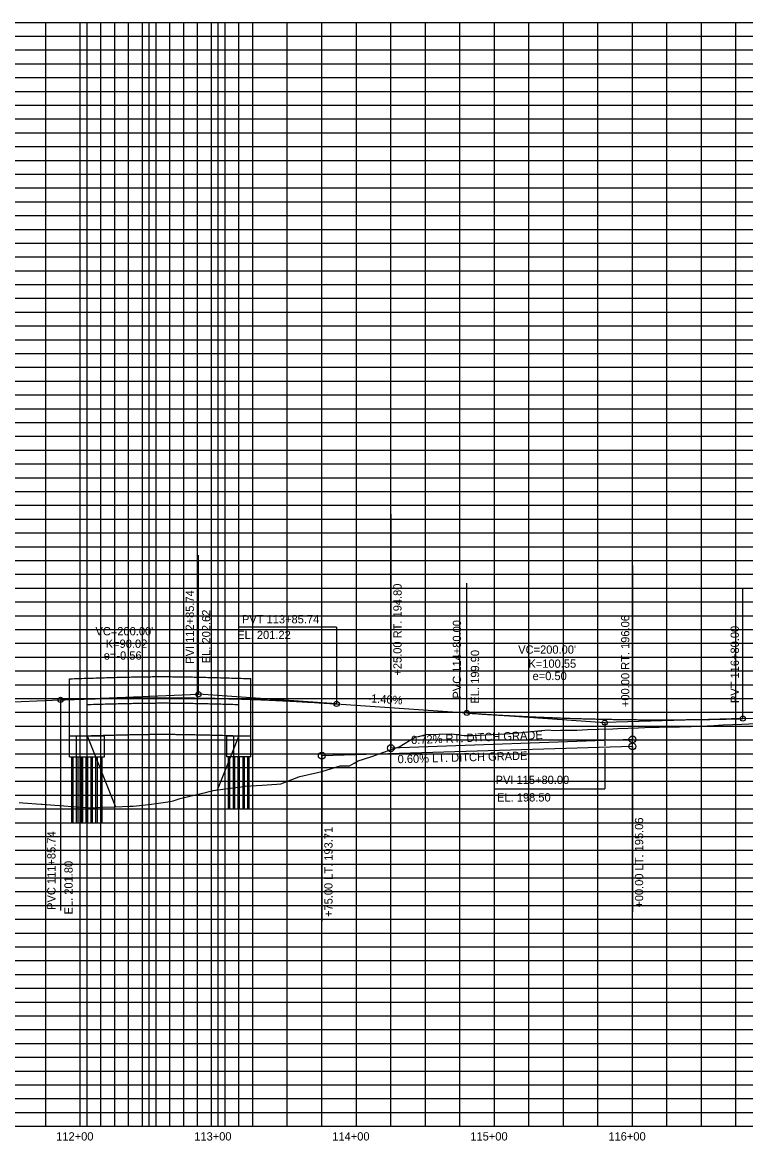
# Model space of a CAD drawing. Extents: x 1384498 to 1391279, y 1965973 to 1976560.
# Drawn here: x 1389607 to 1390131, y 1975299 to 1976110 of the extents above; entities that cross this region are included whole.
import ezdxf

# ---------------------------------------------------------------- set-up
doc = ezdxf.new("R2010")
doc.units = 0
for name, color, linetype in [('Default', 7, 'Continuous'), ('R_Axis_Annotation', 7, 'Continuous'), ('R_Driveway', 7, 'Continuous'), ('R_Exist Surface', 7, 'Continuous'), ('R_Grid', 7, 'Continuous'), ('R_Grid_Minor', 7, 'Continuous'), ('R_Vert Alg', 7, 'Continuous'), ('R_Vert Alg Annot', 7, 'Continuous')]:
    doc.layers.add(name, color=color, linetype=linetype)

msp = doc.modelspace()

# ---------------------------------------------------------------- linework, layer by layer
at = {"layer": 'Default'}
for p, q in [((1389653.79, 1975309.84), (1389653.79, 1976109.84)), ((1389663.79, 1975309.84), (1389663.79, 1976109.84)), ((1389673.79, 1975309.84), (1389673.79, 1976109.84)), ((1389683.79, 1975309.84), (1389683.79, 1976109.84)), ((1389693.79, 1975309.84), (1389693.79, 1976109.84)), ((1389703.79, 1975309.84), (1389703.79, 1976109.84)), ((1389713.79, 1975309.84), (1389713.79, 1976109.84)), ((1389723.79, 1975309.84), (1389723.79, 1976109.84)), ((1389733.79, 1975309.84), (1389733.79, 1976109.84)), ((1389743.79, 1975309.84), (1389743.79, 1976109.84)), ((1389753.79, 1975309.84), (1389753.79, 1976109.84)), ((1389763.79, 1975309.84), (1389763.79, 1976109.84)), ((1388248.79, 1975309.84), (1390648.79, 1975309.84))]:
    msp.add_line(p, q, dxfattribs=at)
at = {"layer": 'R_Driveway'}
for p, q in [((1389641.1, 1975577.58), (1389641.1, 1975634.09)), ((1389653.79, 1975592.82), (1389653.79, 1975634.51)), ((1389763.79, 1975592.8), (1389763.79, 1975634.49)), ((1389772.42, 1975577.54), (1389772.42, 1975634.21)), ((1389666.28, 1975592.59), (1389641.1, 1975592.59)), ((1389646.1, 1975577.58), (1389646.1, 1975592.59)), ((1389653.79, 1975592.82), (1389674.37, 1975541.36)), ((1389666.28, 1975577.58), (1389666.28, 1975592.59)), ((1389763.79, 1975592.8), (1389748.05, 1975553.46)), ((1389755.09, 1975577.54), (1389755.09, 1975592.54)), ((1389772.42, 1975592.54), (1389755.09, 1975592.54)), ((1389760.09, 1975577.54), (1389760.09, 1975592.54)), ((1389641.1, 1975577.58), (1389666.28, 1975577.58)), ((1389642.69, 1975529.84), (1389642.69, 1975577.58)), ((1389643.69, 1975529.84), (1389643.69, 1975577.58)), ((1389646.19, 1975529.84), (1389646.19, 1975577.58)), ((1389647.19, 1975529.84), (1389647.19, 1975577.58)), ((1389649.69, 1975529.84), (1389649.69, 1975577.58)), ((1389650.69, 1975529.84), (1389650.69, 1975577.58)), ((1389653.19, 1975529.84), (1389653.19, 1975577.58)), ((1389654.19, 1975529.84), (1389654.19, 1975577.58)), ((1389656.69, 1975529.84), (1389656.69, 1975577.58)), ((1389657.69, 1975529.84), (1389657.69, 1975577.58)), ((1389660.19, 1975529.84), (1389660.19, 1975577.58)), ((1389661.19, 1975529.84), (1389661.19, 1975577.58)), ((1389663.69, 1975529.84), (1389663.69, 1975577.58)), ((1389664.69, 1975529.84), (1389664.69, 1975577.58)), ((1389772.42, 1975577.54), (1389755.09, 1975577.54)), ((1389756.26, 1975539.84), (1389756.26, 1975577.54)), ((1389757.26, 1975539.84), (1389757.26, 1975577.54)), ((1389759.76, 1975539.84), (1389759.76, 1975577.54)), ((1389760.76, 1975539.84), (1389760.76, 1975577.54)), ((1389763.26, 1975539.84), (1389763.26, 1975577.54)), ((1389764.26, 1975539.84), (1389764.26, 1975577.54)), ((1389766.76, 1975539.84), (1389766.76, 1975577.54)), ((1389767.76, 1975539.84), (1389767.76, 1975577.54)), ((1389770.26, 1975539.84), (1389770.26, 1975577.54)), ((1389771.26, 1975539.84), (1389771.26, 1975577.54))]:
    msp.add_line(p, q, dxfattribs=at)
for points in [[(1389641.1, 1975634.09), (1389684.85, 1975635.67), (1389728.66, 1975635.71), (1389772.42, 1975634.21)], [(1389653.79, 1975615.5), (1389690.44, 1975616.58), (1389727.13, 1975616.58), (1389763.79, 1975615.48)], [(1389653.79, 1975592.82), (1389690.44, 1975593.92), (1389727.13, 1975593.91), (1389763.79, 1975592.8)]]:
    msp.add_open_spline(points, degree=2, dxfattribs=at)
at = {"layer": 'R_Exist Surface'}
for points in [[(1389604.55, 1975544.36), (1389607.11, 1975544.19), (1389620.46, 1975543.28), (1389621.27, 1975543.22), (1389630.42, 1975542.53), (1389633.8, 1975542.27), (1389646.19, 1975541.31), (1389647.14, 1975541.24), (1389649.33, 1975541.07), (1389650.5, 1975540.99), (1389654.54, 1975540.65), (1389660.49, 1975540.85), (1389664.17, 1975540.97), (1389673.58, 1975541.33), (1389673.83, 1975541.34), (1389684.72, 1975541.74), (1389687.17, 1975541.84), (1389689.66, 1975541.93), (1389700.52, 1975543.29), (1389703.65, 1975543.68), (1389703.72, 1975543.69), (1389703.83, 1975543.7), (1389713.86, 1975545.27), (1389716.07, 1975545.61), (1389721.23, 1975547.36), (1389727.2, 1975548.78), (1389740.55, 1975551.96), (1389742.24, 1975552.37), (1389743.84, 1975552.74), (1389744.34, 1975552.85), (1389745.07, 1975553.05), (1389753.89, 1975554.27), (1389767.23, 1975556.12), (1389768.28, 1975556.26), (1389780.58, 1975557.06), (1389791.32, 1975557.77), (1389793.92, 1975558.06), (1389794.14, 1975558.09), (1389807.26, 1975563.08), (1389807.98, 1975563.35), (1389820.61, 1975566.15), (1389823.8, 1975566.84), (1389833.95, 1975570.11), (1389837.03, 1975571.11), (1389843.79, 1975571.13), (1389847.29, 1975573.04), (1389850.22, 1975574.59), (1389853.92, 1975575.98), (1389860.64, 1975578.15), (1389864.54, 1975579.38), (1389872.73, 1975582.48), (1389879.84, 1975584.82), (1389891.75, 1975591.94), (1389893.9, 1975592.21), (1389899.41, 1975593.85), (1389917.54, 1975594.13), (1389917.62, 1975594.13), (1389917.62, 1975594.13), (1389917.65, 1975594.11), (1389917.71, 1975594.11), (1389926.8, 1975593.11), (1389932.54, 1975592.96), (1389938.09, 1975593.21), (1389960.46, 1975594.49), (1389962.65, 1975594.59), (1389966.32, 1975594.88), (1389975.1, 1975596), (1389985.37, 1975596.96), (1389987.73, 1975597.1), (1389991.74, 1975596.6), (1389996.76, 1975596.89), (1390008.49, 1975596.99), (1390016.3, 1975597.39), (1390024.26, 1975597.51), (1390034.55, 1975597.91), (1390038.23, 1975598.07), (1390053.02, 1975598.67), (1390053.11, 1975598.68), (1390057.73, 1975598.79), (1390067.77, 1975599.04), (1390068.15, 1975599.06), (1390082.82, 1975599.24)], [(1390082.82, 1975599.24), (1390091.38, 1975599.54), (1390098.09, 1975599.78), (1390107.69, 1975600.34), (1390110.87, 1975600.5), (1390113.11, 1975600.58), (1390114.47, 1975600.68), (1390128.08, 1975601.16), (1390138.24, 1975601.8)]]:
    msp.add_lwpolyline(points, dxfattribs=at)
at = {"layer": 'R_Grid'}
for p, q in [((1388248.79, 1976109.84), (1391048.79, 1976109.84)), ((1388248.79, 1976109.84), (1391048.79, 1976109.84)), ((1389648.79, 1975309.84), (1389648.79, 1976109.84)), ((1389748.79, 1975309.84), (1389748.79, 1976109.84)), ((1389848.79, 1975309.84), (1389848.79, 1976109.84)), ((1389948.79, 1975309.84), (1389948.79, 1976109.84)), ((1390048.79, 1975309.84), (1390048.79, 1976109.84)), ((1388248.79, 1976059.84), (1391048.79, 1976059.84)), ((1388248.79, 1976009.84), (1391048.79, 1976009.84)), ((1388248.79, 1975959.84), (1391048.79, 1975959.84)), ((1388248.79, 1975909.84), (1391048.79, 1975909.84)), ((1388248.79, 1975859.84), (1391048.79, 1975859.84)), ((1388248.79, 1975809.84), (1391048.79, 1975809.84)), ((1388248.79, 1975759.84), (1391048.79, 1975759.84)), ((1388248.79, 1975709.84), (1391048.79, 1975709.84)), ((1388248.79, 1975659.84), (1391048.79, 1975659.84)), ((1388248.79, 1975609.84), (1391048.79, 1975609.84)), ((1388248.79, 1975559.84), (1391048.79, 1975559.84)), ((1388248.79, 1975509.84), (1391048.79, 1975509.84)), ((1388248.79, 1975459.84), (1391048.79, 1975459.84)), ((1388248.79, 1975409.84), (1391048.79, 1975409.84)), ((1388248.79, 1975359.84), (1391048.79, 1975359.84)), ((1388248.79, 1975309.84), (1391048.79, 1975309.84))]:
    msp.add_line(p, q, dxfattribs=at)
at = {"layer": 'R_Grid_Minor'}
for p, q in [((1389623.79, 1975309.84), (1389623.79, 1976109.84)), ((1389673.79, 1975309.84), (1389673.79, 1976109.84)), ((1389698.79, 1975309.84), (1389698.79, 1976109.84)), ((1389723.79, 1975309.84), (1389723.79, 1976109.84)), ((1389773.79, 1975309.84), (1389773.79, 1976109.84)), ((1389798.79, 1975309.84), (1389798.79, 1976109.84)), ((1389823.79, 1975309.84), (1389823.79, 1976109.84)), ((1389873.79, 1975309.84), (1389873.79, 1976109.84)), ((1389898.79, 1975309.84), (1389898.79, 1976109.84)), ((1389923.79, 1975309.84), (1389923.79, 1976109.84)), ((1389973.79, 1975309.84), (1389973.79, 1976109.84)), ((1389998.79, 1975309.84), (1389998.79, 1976109.84)), ((1390023.79, 1975309.84), (1390023.79, 1976109.84)), ((1390073.79, 1975309.84), (1390073.79, 1976109.84)), ((1390098.79, 1975309.84), (1390098.79, 1976109.84)), ((1390123.79, 1975309.84), (1390123.79, 1976109.84)), ((1388248.79, 1976099.84), (1391048.79, 1976099.84)), ((1388248.79, 1976089.84), (1391048.79, 1976089.84)), ((1388248.79, 1976079.84), (1391048.79, 1976079.84)), ((1388248.79, 1976069.84), (1391048.79, 1976069.84)), ((1388248.79, 1976049.84), (1391048.79, 1976049.84)), ((1388248.79, 1976039.84), (1391048.79, 1976039.84)), ((1388248.79, 1976029.84), (1391048.79, 1976029.84)), ((1388248.79, 1976019.84), (1391048.79, 1976019.84)), ((1388248.79, 1975999.84), (1391048.79, 1975999.84)), ((1388248.79, 1975989.84), (1391048.79, 1975989.84)), ((1388248.79, 1975979.84), (1391048.79, 1975979.84)), ((1388248.79, 1975969.84), (1391048.79, 1975969.84)), ((1388248.79, 1975949.84), (1391048.79, 1975949.84)), ((1388248.79, 1975939.84), (1391048.79, 1975939.84)), ((1388248.79, 1975929.84), (1391048.79, 1975929.84)), ((1388248.79, 1975919.84), (1391048.79, 1975919.84)), ((1388248.79, 1975899.84), (1391048.79, 1975899.84)), ((1388248.79, 1975889.84), (1391048.79, 1975889.84)), ((1388248.79, 1975879.84), (1391048.79, 1975879.84)), ((1388248.79, 1975869.84), (1391048.79, 1975869.84)), ((1388248.79, 1975849.84), (1391048.79, 1975849.84)), ((1388248.79, 1975839.84), (1391048.79, 1975839.84)), ((1388248.79, 1975829.84), (1391048.79, 1975829.84)), ((1388248.79, 1975819.84), (1391048.79, 1975819.84)), ((1388248.79, 1975799.84), (1391048.79, 1975799.84)), ((1388248.79, 1975789.84), (1391048.79, 1975789.84)), ((1388248.79, 1975779.84), (1391048.79, 1975779.84)), ((1388248.79, 1975769.84), (1391048.79, 1975769.84)), ((1388248.79, 1975749.84), (1391048.79, 1975749.84)), ((1388248.79, 1975739.84), (1391048.79, 1975739.84)), ((1388248.79, 1975729.84), (1391048.79, 1975729.84)), ((1388248.79, 1975719.84), (1391048.79, 1975719.84)), ((1388248.79, 1975699.84), (1391048.79, 1975699.84)), ((1388248.79, 1975689.84), (1391048.79, 1975689.84)), ((1388248.79, 1975679.84), (1391048.79, 1975679.84)), ((1388248.79, 1975669.84), (1391048.79, 1975669.84)), ((1388248.79, 1975649.84), (1391048.79, 1975649.84)), ((1388248.79, 1975639.84), (1391048.79, 1975639.84)), ((1388248.79, 1975629.84), (1391048.79, 1975629.84)), ((1388248.79, 1975619.84), (1391048.79, 1975619.84)), ((1388248.79, 1975599.84), (1391048.79, 1975599.84)), ((1388248.79, 1975589.84), (1391048.79, 1975589.84)), ((1388248.79, 1975579.84), (1391048.79, 1975579.84)), ((1388248.79, 1975569.84), (1391048.79, 1975569.84)), ((1388248.79, 1975549.84), (1391048.79, 1975549.84)), ((1388248.79, 1975539.84), (1391048.79, 1975539.84)), ((1388248.79, 1975529.84), (1391048.79, 1975529.84)), ((1388248.79, 1975519.84), (1391048.79, 1975519.84)), ((1388248.79, 1975499.84), (1391048.79, 1975499.84)), ((1388248.79, 1975489.84), (1391048.79, 1975489.84)), ((1388248.79, 1975479.84), (1391048.79, 1975479.84)), ((1388248.79, 1975469.84), (1391048.79, 1975469.84)), ((1388248.79, 1975449.84), (1391048.79, 1975449.84)), ((1388248.79, 1975439.84), (1391048.79, 1975439.84)), ((1388248.79, 1975429.84), (1391048.79, 1975429.84)), ((1388248.79, 1975419.84), (1391048.79, 1975419.84)), ((1388248.79, 1975399.84), (1391048.79, 1975399.84)), ((1388248.79, 1975389.84), (1391048.79, 1975389.84)), ((1388248.79, 1975379.84), (1391048.79, 1975379.84)), ((1388248.79, 1975369.84), (1391048.79, 1975369.84)), ((1388248.79, 1975349.84), (1391048.79, 1975349.84)), ((1388248.79, 1975339.84), (1391048.79, 1975339.84)), ((1388248.79, 1975329.84), (1391048.79, 1975329.84)), ((1388248.79, 1975319.84), (1391048.79, 1975319.84))]:
    msp.add_line(p, q, dxfattribs=at)
at = {"layer": 'R_Vert Alg'}
for p, q in [((1389053.79, 1975594.97), (1389634.53, 1975618.83)), ((1389834.53, 1975615.94), (1389928.79, 1975609.34)), ((1390128.79, 1975605.28), (1390198.79, 1975607.34)), ((1390048.79, 1975590.14), (1389873.79, 1975583.84)), ((1390048.79, 1975585.14), (1389823.79, 1975578.39))]:
    msp.add_line(p, q, dxfattribs=at)
for points in [[(1389634.53, 1975618.83), (1389638.53, 1975618.99), (1389642.53, 1975619.14), (1389646.53, 1975619.28), (1389650.53, 1975619.42), (1389654.53, 1975619.54), (1389658.53, 1975619.66), (1389662.53, 1975619.76), (1389666.53, 1975619.86), (1389670.53, 1975619.95), (1389674.53, 1975620.03), (1389678.53, 1975620.1), (1389682.53, 1975620.16), (1389686.53, 1975620.22), (1389690.53, 1975620.26), (1389694.53, 1975620.3), (1389698.53, 1975620.32), (1389702.53, 1975620.34), (1389706.53, 1975620.35), (1389710.53, 1975620.35), (1389714.53, 1975620.34), (1389718.53, 1975620.32), (1389722.53, 1975620.29), (1389726.53, 1975620.26), (1389730.53, 1975620.21), (1389734.53, 1975620.16), (1389738.53, 1975620.1), (1389742.53, 1975620.03), (1389746.53, 1975619.95), (1389750.53, 1975619.86), (1389754.53, 1975619.76), (1389758.53, 1975619.65), (1389762.53, 1975619.54), (1389766.53, 1975619.41), (1389770.53, 1975619.28), (1389774.53, 1975619.14), (1389778.53, 1975618.99), (1389782.53, 1975618.83), (1389786.53, 1975618.66), (1389790.53, 1975618.48), (1389794.53, 1975618.29), (1389798.53, 1975618.1), (1389802.53, 1975617.89), (1389806.53, 1975617.68), (1389810.53, 1975617.46), (1389814.53, 1975617.23), (1389818.53, 1975616.99), (1389822.53, 1975616.74), (1389826.53, 1975616.48), (1389830.53, 1975616.21), (1389834.53, 1975615.94)], [(1389928.79, 1975609.34), (1389932.79, 1975609.06), (1389936.79, 1975608.79), (1389940.79, 1975608.53), (1389944.79, 1975608.28), (1389948.79, 1975608.04), (1389952.79, 1975607.8), (1389956.79, 1975607.57), (1389960.79, 1975607.35), (1389964.79, 1975607.14), (1389968.79, 1975606.94), (1389972.79, 1975606.74), (1389976.79, 1975606.55), (1389980.79, 1975606.37), (1389984.79, 1975606.2), (1389988.79, 1975606.03), (1389992.79, 1975605.88), (1389996.79, 1975605.73), (1390000.79, 1975605.59), (1390004.79, 1975605.45), (1390008.79, 1975605.33), (1390012.79, 1975605.21), (1390016.79, 1975605.1), (1390020.79, 1975605), (1390024.79, 1975604.91), (1390028.79, 1975604.82), (1390032.79, 1975604.75), (1390036.79, 1975604.68), (1390040.79, 1975604.62), (1390044.79, 1975604.56), (1390048.79, 1975604.52), (1390052.79, 1975604.48), (1390056.79, 1975604.45), (1390060.79, 1975604.43), (1390064.79, 1975604.42), (1390068.79, 1975604.41), (1390072.79, 1975604.41), (1390076.79, 1975604.42), (1390080.79, 1975604.44), (1390084.79, 1975604.47), (1390088.79, 1975604.5), (1390092.79, 1975604.55), (1390096.79, 1975604.6), (1390100.79, 1975604.65), (1390104.79, 1975604.72), (1390108.79, 1975604.79), (1390112.79, 1975604.88), (1390116.79, 1975604.97), (1390120.79, 1975605.06), (1390124.79, 1975605.17), (1390128.79, 1975605.28)]]:
    msp.add_spline(points, degree=3, dxfattribs=at)
at = {"layer": 'R_Vert Alg Annot'}
for p, q in [((1389873.79, 1975753.34), (1389873.79, 1975622.77)), ((1389734.53, 1975632.94), (1389734.53, 1975723.78)), ((1390048.79, 1975716.18), (1390048.79, 1975605.42)), ((1389928.79, 1975619.34), (1389928.79, 1975703.34)), ((1390128.79, 1975615.28), (1390128.79, 1975699.28)), ((1389834.53, 1975671.59), (1389764.23, 1975671.59)), ((1389834.53, 1975671.59), (1389834.53, 1975615.94)), ((1389734.53, 1975622.94), (1389734.53, 1975632.94)), ((1389634.53, 1975618.83), (1389734.53, 1975622.94)), ((1389834.53, 1975615.94), (1389734.53, 1975622.94)), ((1389634.53, 1975618.83), (1389634.53, 1975608.83)), ((1389928.79, 1975609.34), (1389928.79, 1975619.34)), ((1390128.79, 1975605.28), (1390128.79, 1975615.28)), ((1389634.53, 1975608.83), (1389634.53, 1975466.3)), ((1389873.79, 1975611.53), (1389873.79, 1975583.84)), ((1389928.79, 1975609.34), (1390028.79, 1975602.34)), ((1390128.79, 1975605.28), (1390028.79, 1975602.34)), ((1390028.79, 1975602.34), (1390028.79, 1975589.99)), ((1390048.79, 1975602.33), (1390048.79, 1975590.14)), ((1390028.79, 1975588.9), (1390028.79, 1975585.49)), ((1390028.79, 1975583.61), (1390028.79, 1975554.37)), ((1390048.79, 1975585.14), (1390048.79, 1975465.22)), ((1389823.79, 1975578.39), (1389823.79, 1975458.47)), ((1389948.47, 1975554.37), (1390028.79, 1975554.37))]:
    msp.add_line(p, q, dxfattribs=at)
for centre, radius in [((1389734.53, 1975622.94), 1.85), ((1389634.53, 1975618.83), 1.85), ((1389834.53, 1975615.94), 1.85), ((1389928.79, 1975609.34), 1.85), ((1390128.79, 1975605.28), 1.85), ((1390028.79, 1975602.34), 1.85), ((1390048.79, 1975590.14), 2.5), ((1389873.79, 1975583.84), 2.5), ((1390048.79, 1975585.14), 2.5), ((1389823.79, 1975578.39), 2.5)]:
    msp.add_circle(centre, radius, dxfattribs=at)

# ---------------------------------------------------------------- texts
at = {"layer": 'R_Axis_Annotation'}
for s, p in [('112+00', (1389631.38, 1975299.49)), ('113+00', (1389731.38, 1975299.49)), ('114+00', (1389831.38, 1975299.49)), ('115+00', (1389931.38, 1975299.49)), ('116+00', (1390031.38, 1975299.49))]:
    msp.add_text(s, height=6, dxfattribs=at).set_placement(p)
at = {"layer": 'R_Vert Alg Annot'}
for s, rotation, p in [('PVI 112+85.74', 90, (1389731.18, 1975644.99)), ('+25.00 RT. 194.80', 90, (1389881.57, 1975636.42)), ('EL. 202.62', 90, (1389743.03, 1975645.43)), ('+00.00 RT. 196.06', 90, (1390046.54, 1975613.6)), ('PVC 114+80.00', 90, (1389924.65, 1975619.8)), ('PVT 116+80.00', 90, (1390125.89, 1975616.51)), (' EL. 199.90', 90, (1389937.72, 1975613.95)), ('-1.40%', 356.04001, (1389856.67, 1975617.21)), ('0.72% RT. DITCH GRADE', 2.25876, (1389888.58, 1975586.72)), ('0.60% LT. DITCH GRADE', 1.60842, (1389878.77, 1975572.85)), ('PVI 115+80.00', 360, (1389949.68, 1975557.86)), ('EL. 198.50', 360, (1389950.74, 1975545.18)), ('+00.00 LT. 195.06', 90, (1390056.57, 1975468.22)), ('+75.00 LT. 193.71', 90, (1389831.57, 1975461.47)), ('PVC 111+85.74', 90, (1389630.9, 1975466.63)), (' EL. 201.80', 90, (1389643.33, 1975461.12))]:
    msp.add_text(s, height=6, rotation=rotation, dxfattribs=at).set_placement(p)
for s, p in [('PVT 113+85.74', (1389765.93, 1975674.28)), ("VC=200.00'", (1389659.83, 1975665.6)), (' EL. 201.22', (1389760.25, 1975662.92)), ('K=90.02', (1389667.27, 1975656.55)), ("VC=200.00'", (1389966.04, 1975652.29)), ("e=-0.56'", (1389665.83, 1975647.99)), ('K=100.55', (1389973.45, 1975642.1)), ('e=0.50', (1389976.46, 1975633.16))]:
    msp.add_text(s, height=6, dxfattribs=at).set_placement(p)

doc.saveas('drawing.dxf')
